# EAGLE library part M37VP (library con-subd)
SUB-D
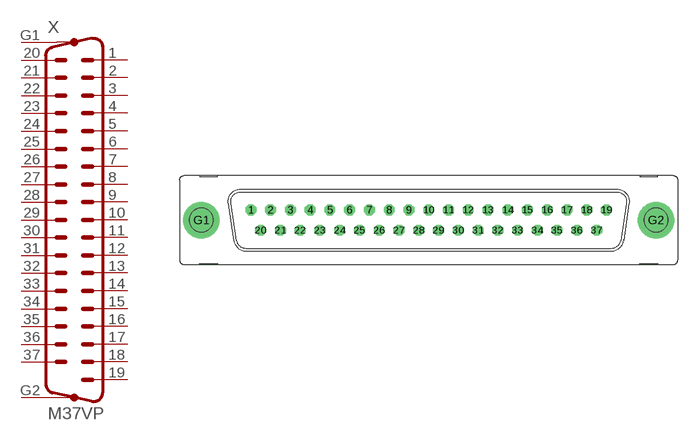
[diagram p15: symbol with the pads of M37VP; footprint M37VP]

Designator prefix X

## M37VP (OC_FARNELL: unknown; OC_NEWARK: unknown)  [M37VP]
1  1  pas
2  2  pas
3  3  pas
4  4  pas
5  5  pas
6  6  pas
7  7  pas
8  8  pas
9  9  pas
10  10  pas
11  11  pas
12  12  pas
13  13  pas
14  14  pas
15  15  pas
16  16  pas
17  17  pas
18  18  pas
19  19  pas
20  20  pas
21  21  pas
22  22  pas
23  23  pas
24  24  pas
25  25  pas
26  26  pas
27  27  pas
28  28  pas
29  29  pas
30  30  pas
31  31  pas
32  32  pas
33  33  pas
34  34  pas
35  35  pas
36  36  pas
37  37  pas
G1  G1  pas
G2  G2  pas

## Footprint M37VP (pad centres in mm)
SUB-D
drill 1.016 octagon: 1 -24.841,1.422; 2 -22.098,1.422; 3 -19.329,1.422; 4 -16.561,1.422; 5 -13.818,1.422; 6 -11.049,1.422; 7 -8.28,1.422; 8 -5.512,1.422; 9 -2.769,1.422; 10 0,1.422; 11 2.769,1.422; 12 5.512,1.422; 13 8.28,1.422; 14 11.049,1.422; 15 13.792,1.422; 16 16.561,1.422; 17 19.329,1.422; 18 22.073,1.422; 19 24.841,1.422; 20 -23.47,-1.422; 21 -20.701,-1.422; 22 -17.958,-1.422; 23 -15.189,-1.422; 24 -12.421,-1.422; 25 -9.652,-1.422; 26 -6.909,-1.422; 27 -4.14,-1.422; 28 -1.372,-1.422; 29 1.372,-1.422; 30 4.14,-1.422; 31 6.909,-1.422; 32 9.652,-1.422; 33 12.421,-1.422; 34 15.189,-1.422; 35 17.932,-1.422; 36 20.701,-1.422; 37 23.47,-1.422
drill 3.302 pad 5.08 round: G1 -31.75,0; G2 31.75,0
